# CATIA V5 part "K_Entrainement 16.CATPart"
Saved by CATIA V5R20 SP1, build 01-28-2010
Part number: Entrainement 16
Bounding box of the stored display mesh (mm): x -30 to 30, y -352.201 to 352.201, z 0 to 109.606
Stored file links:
  G:\Khaled_CFAO_2011\SIL\SIL_GR1\gperrin\Khaled\CAD_CATIA\Khaled\K_Entrainement 16.CATPart
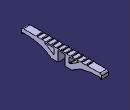
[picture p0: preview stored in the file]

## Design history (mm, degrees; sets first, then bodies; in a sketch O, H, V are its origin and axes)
Body1 (main body)
  Sketch1 on yz-plane, origin (0, 0, 0), H (0, 1, 0), V (0, 0, 1)
    point P1 (30, 0)
    line L1 (30, 0) -> (90, 0)
    line L2 (30, 90) -> (30, 0)
    line L3 (72.858, 90) -> (146.2201, 90)
    line L4 (182.9277, 50.0949) -> (239.6277, 61.7707)
    arc A1 centre (202.6763, -45.8082) radius 97.9154 from (182.9277, 50.0949) to (151.534, 37.6895) ccw
    line L5 (66.1125, 83.2545) -> (66.1125, 42.6018)
    arc A2 centre (146.2201, 87.8988) radius 2.1012 from (147.3175, 86.107) to (146.2201, 90) ccw
    point P7 (147.3175, 86.107)
    arc A3 centre (69.604, 42.6018) radius 3.4915 from (71.4276, 39.6244) to (66.1125, 42.6018) cw
    arc A4 centre (72.858, 83.2545) radius 6.7455 from (66.1125, 83.2545) to (72.858, 90) cw
    arc A5 centre (348.7919, 58.5785) radius 2.8764 from (345.9645, 58.0499) to (351.6677, 58.5217) ccw
    line L6 (351.6677, 58.5217) -> (352.2014, 85.5461)
    point P14 (351.6677, 58.5217)
    arc A6 centre (337.0496, 85.8453) radius 15.1547 from (352.2014, 85.5461) to (337.0496, 101) ccw
    point P19 (351.6677, 58.5217)
    arc A7 centre (220, 106) radius 3.6056 from (223.4641, 107) to (216.5359, 107) ccw
    line L7 (216.5359, 107) -> (214.8038, 101)
    point P22 (225.1962, 101)
    line L8 (223.4641, 107) -> (225.1962, 101)
    arc A8 centre (175, 106) radius 3.6056 from (171.5359, 107) to (178.4641, 107) cw
    line L9 (178.4641, 107) -> (180.1962, 101)
    line L10 (171.5359, 107) -> (169.8038, 101)
    arc A9 centre (130, 106) radius 3.6056 from (133.4641, 107) to (126.5359, 107) ccw
    line L11 (126.5359, 107) -> (124.8038, 101)
    line L12 (133.4641, 107) -> (135.1962, 101)
    arc A10 centre (40, 106) radius 3.6056 from (43.4641, 107) to (36.5359, 107) ccw
    line L13 (36.5359, 107) -> (34.8038, 101)
    line L14 (43.4641, 107) -> (45.1962, 101)
    arc A11 centre (85, 106) radius 3.6056 from (81.5359, 107) to (88.4641, 107) cw
    line L15 (88.4641, 107) -> (90.1962, 101)
    line L16 (81.5359, 107) -> (79.8038, 101)
    arc A12 centre (0, 106) radius 3.6056 from (3.4641, 107) to (0, 109.6056) ccw
    line L17 (3.4641, 107) -> (5.1962, 101)
    arc A13 centre (338.7633, 61.6195) radius 7.2467 from (346.0014, 61.972) to (338.7633, 68.8662) ccw
    line L18 (309.2644, 68.8662) -> (338.7633, 68.8662)
    arc A14 centre (309.2644, -276.3984) radius 345.2646 from (309.2644, 68.8662) to (239.6277, 61.7707) ccw
    line L19 (346.0014, 61.972) -> (345.9645, 58.0499)
    line L20 (0, 109.6056) -> (0, 90)
    line L21 (151.534, 37.6895) -> (90, 0)
    line L22 (30, 90) -> (0, 90)
    line L23 (169.8038, 101) -> (135.1962, 101)
    line L24 (124.8038, 101) -> (90.1962, 101)
    line L25 (79.8038, 101) -> (45.1962, 101)
    line L26 (5.1962, 101) -> (34.8038, 101)
    line L27 (214.8038, 101) -> (180.1962, 101)
    line L28 (71.4276, 39.6244) -> (147.3175, 86.107)
    point P46 (147.3175, 86.107)
    line L29 (337.0496, 101) -> (225.1962, 101)
    point P47 (225.1962, 101)
    distance L2 V = 30
    length L1 = 60
    length L2 = 90
    radius A1 = 97.9154
    radius A2 = 2.1012
    radius A3 = 3.4915
    radius A4 = 6.7455
    radius A6 = 15.1547
    radius A14 = 345.2646
    distance L3 L24 = 11
    coincidence: P1 H, P14 A5, L6 P19, P46 A2, P47 L8, P7 P46, P22 P47, P14 P19
    horizontal: L1 H, L3 H, L23 H, L24 H, L25 H, L26 H
    vertical: L2 V, L5 V, L20 V
    tangency: A1 L4, A2 L3, A3 L5, A4 L5, A4 L3, L6 A5, A6 L6, L7 A7, L18 A13, A14 L18, A14 L4, L21 A1, L22 A4, L27 A6, L28 A2, L29 A6
  Pad1: profile Sketch1, direction (1, 0, 0), length 30, mirrored extent
  Mirror1: of Pad1, Sketch1, about zx-plane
